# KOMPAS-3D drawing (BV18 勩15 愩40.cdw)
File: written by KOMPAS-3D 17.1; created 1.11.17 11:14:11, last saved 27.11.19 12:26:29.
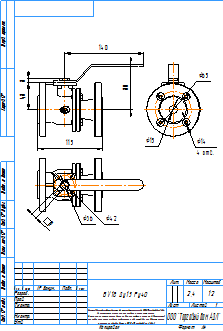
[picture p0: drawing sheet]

Sheet 1: A4, portrait

Title block, sheet 1: name: BV18 Ду15 Ру40; material: Сталь 10  ГОСТ 1050-88; mass: 2,4; sheets: 1; sheet format: A4; stored path: C:\Users\kka\KOMPAS_Work\!Trash\BV18\KOMPAS 2D\BV18 Ду50 Ру40.cdw

Views: Проекционный вид 4, Проекционный вид 5
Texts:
  kka
  adl
  Рама для чертежей
  Лит-Масса-Масштаб
  Материал-Предприятие
  Масштаб
  Изм.
  Лист
  № докум.
  Подп.
  Дата
  Лит.
  Разраб.
  Пров.
  Т.контр.
  Листов
  Внимание! Данный продукт является объектом авторского права ООО «Торговый Дом АДЛ».
  Запрещается изменение, копирование, распространение
  (в том числе путем копирования на другие сайты и ресурсы в Интернете)
  или любое иное использование информации и объектов без предварительного
  согласия правообладателя (ООО «Торговый Дом АДЛ»).
  Н.контр.
  Утв.
  ООО "Торговый дом АДЛ"
  Изменение
  Номер документа
  Подпись
  Обозначение документа
  Наименование изделия
  Масса изделия по ГОСТ 2.109-73
  Порядковый номер листа
  Общее количество листов в документе
  Характер работы, выполненной лицом, подписавшим документ
  Наименование или индекс предприятия, выпускающего документ
  Инв. № подл.
  Подп. и дата
  Взам. инв. №
  Инв. № дубл.
  Инвентарный номер подлинника по ГОСТ 2.501-68
  Подпись принявшего подлинник в отдел технической документации
  Инвентарный номер подлинника, взамен которого выпущен данный подлинник
  Инвентарный номер дубликата по ГОСТ 2.502-68
  Подпись принявшего дубликат в отдел технической документации
  Справ. №
  Перв. примен.
  Обозначение документа, взамен или на основании которого выпущен данный документ
  Обозначение документа, в котором впервые записан данный документ
  Подпись лица, копировавшего чертеж
  Обозначение формата листа
  !Рама для чертежа
Dimensions and other numbers on the sheet: 115; 140; 80; 48; 8; 65; 14; 4 отв.; 15; 1:2; 1; 2,4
